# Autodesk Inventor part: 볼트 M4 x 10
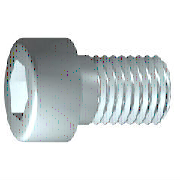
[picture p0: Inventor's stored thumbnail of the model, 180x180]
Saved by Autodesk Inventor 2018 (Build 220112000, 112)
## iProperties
IsCustomPart: 1
Created: 2012-02
Part Number: 볼트 M4 x 10
Material: 강철, 연강
Description: 6각머리 태핑 나사
Document SubType Name: Modeling
Standard: KS B 1003
Designer: mduedu
Standards Organization: KS
Language: ko-KR
Size Designation: M 4 x 10
Categories: <MemberInstance><Categories><Category DisplayName="조임쇠" InternalName="e4da775c-781d-43d5-af7c-5136215cf5a6" Mnemonic="FSTN"><Category DisplayName="볼트" InternalN
Density: 7.85 g/cm^3
Appearance: 강철
Mass: 2.03451 g
Surface Area: 3.0572 cm^2
Volume: 0.259174 cm^3
Author: mduedu
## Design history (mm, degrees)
sketch "스케치1"
  geometry: L1 (-1, 0)-(10, 0); L2 (10, 0)-(10, 2); L3 (10, 2)-(1.75, 2); L4 (1.75, 2)-(1.32, 2); L5 (1.32, 2)-(0, 2); L6 (0, 2)-(0, 3.5); L7 (0, 3.5)-(-4, 3.5); L8 (-4, 3.5)-(-4, 1.732); L9 (-4, 1.732)-(-2, 1.732); L10 (-2, 1.732)-(-1, 0); L11 (-6.8, 0)-(12.8, 0) reference; L12 (0, -0.7)-(0, 4.2) reference; L13 (1.75, 2)-(0, 2)
  constraints: 22 end point, 6 parallel, 2 collinear, 2 perpendicular, 1 horizontal, 1 point on line
  dimensions: "d1" = 8.25 distance from line of L3.end L2 (= GEL); "d2" = 0.42952 distance of L4.end L3.end (computed from GAL); "d3" = 4 distance between parallel lines of L8 L6 (= KOH); "d4" = 2 distance of L8.end L9.end (= INTI); "d5" = 60 deg angle of L10 L1; "d6" = 4 diameter of L3 L1 (= GD); "d7" = 4 diameter of L5 L1 (= BDM); "d8" = 3.4641 diameter of L9 L1 (= 1.1547 x SW); "d9" = 7 diameter of L7 L1 (= KOD); "d26" = 10 distance between parallel lines of L12 L2 (= NLG)
revolve "본체" sketch "스케치1" stored, may be unused: angle "d10" = 90 deg
sketch "스케치2"
  geometry: L1 (0, -4.9)-(0, 4.9) reference; L2 (-4.9, 0)-(4.9, 0) reference; L3 (1.732, 0)-(0.866, -1.5); L4 (0.866, -1.5)-(-0.866, -1.5); L5 (-0.866, -1.5)-(-1.732, 0); L6 (-1.732, 0)-(-0.866, 1.5); L7 (-0.866, 1.5)-(0.866, 1.5); L8 (0.866, 1.5)-(1.732, 0); 2 further points
  constraints: 12 end point, 1 coincident, 1 horizontal alignment, 1 point on line, 12 other
extrude "슬롯" join sketch "스케치2" stored distance "d11" = 10; taper "d12" = 0 deg
workplane "Work Plane1"
fillet "Fillet2" dims "d30" = 0.1 (= R)
body "Solid1"
fillet "모깎기1" dims "d17" = 0.4 (= RR)
feature "스레드" dims "d13" = 8.25 (= GEL), "d14" = 0
chamfer "모따기1" distance "d15" = 0.42941 (= -0.5 x SPD + 0.5 x GD); stored, may be unused: second distance "d16" = 0.42941 (= GUL), angle "d27" = 45 deg
other parameters: "GD" = 4 (= NND) [user parameter; used in 2 equation terms], "NLG" = 10 [user parameter; used in 1 equation term], "GEL" = 8.25 [user parameter; used in 2 equation terms], "KOD" = 7 [user parameter; used in 1 equation term], "KOH" = 4 [user parameter; used in 1 equation term], "INTI" = 2 [user parameter; used in 1 equation term], "GAL" = 0.42941 (= 0.61345 x PTC) [user parameter; used in 1 equation term], "GUL" = 0.42941 (= 0.61345 x PTC) [user parameter; used in 1 equation term], "BDM" = 4 (= NND) [user parameter; used in 1 equation term], "SW" = 3 [user parameter; used in 2 equation terms], "RR" = 0.4 [user parameter; used in 1 equation term], "SPD" = 3.14117 (= NND - 1.2269 x PTC) [user parameter; used in 1 equation term], "d19" = 0, "d28" = 0, "d29" = 0, "R" = 0.1 [user parameter; used in 1 equation term], "PHH" = 0.2 [user parameter], "GD1" = 3.14117 (= THREADDIA - 1.2269 x PTC) [user parameter], "THREADDIA" = 4 [user parameter; used in 1 equation term], "FAWI" = 45 deg [user parameter], "TPU" = 14.28571 (computed from PTC) [user parameter], "PTC" = 0.7 [user parameter; used in 5 equation terms], "NND" = 4 [user parameter; used in 3 equation terms], "TOA" = 30 deg [user parameter], "E0" = 3.465 (= 1.155 x SW) [user parameter]
